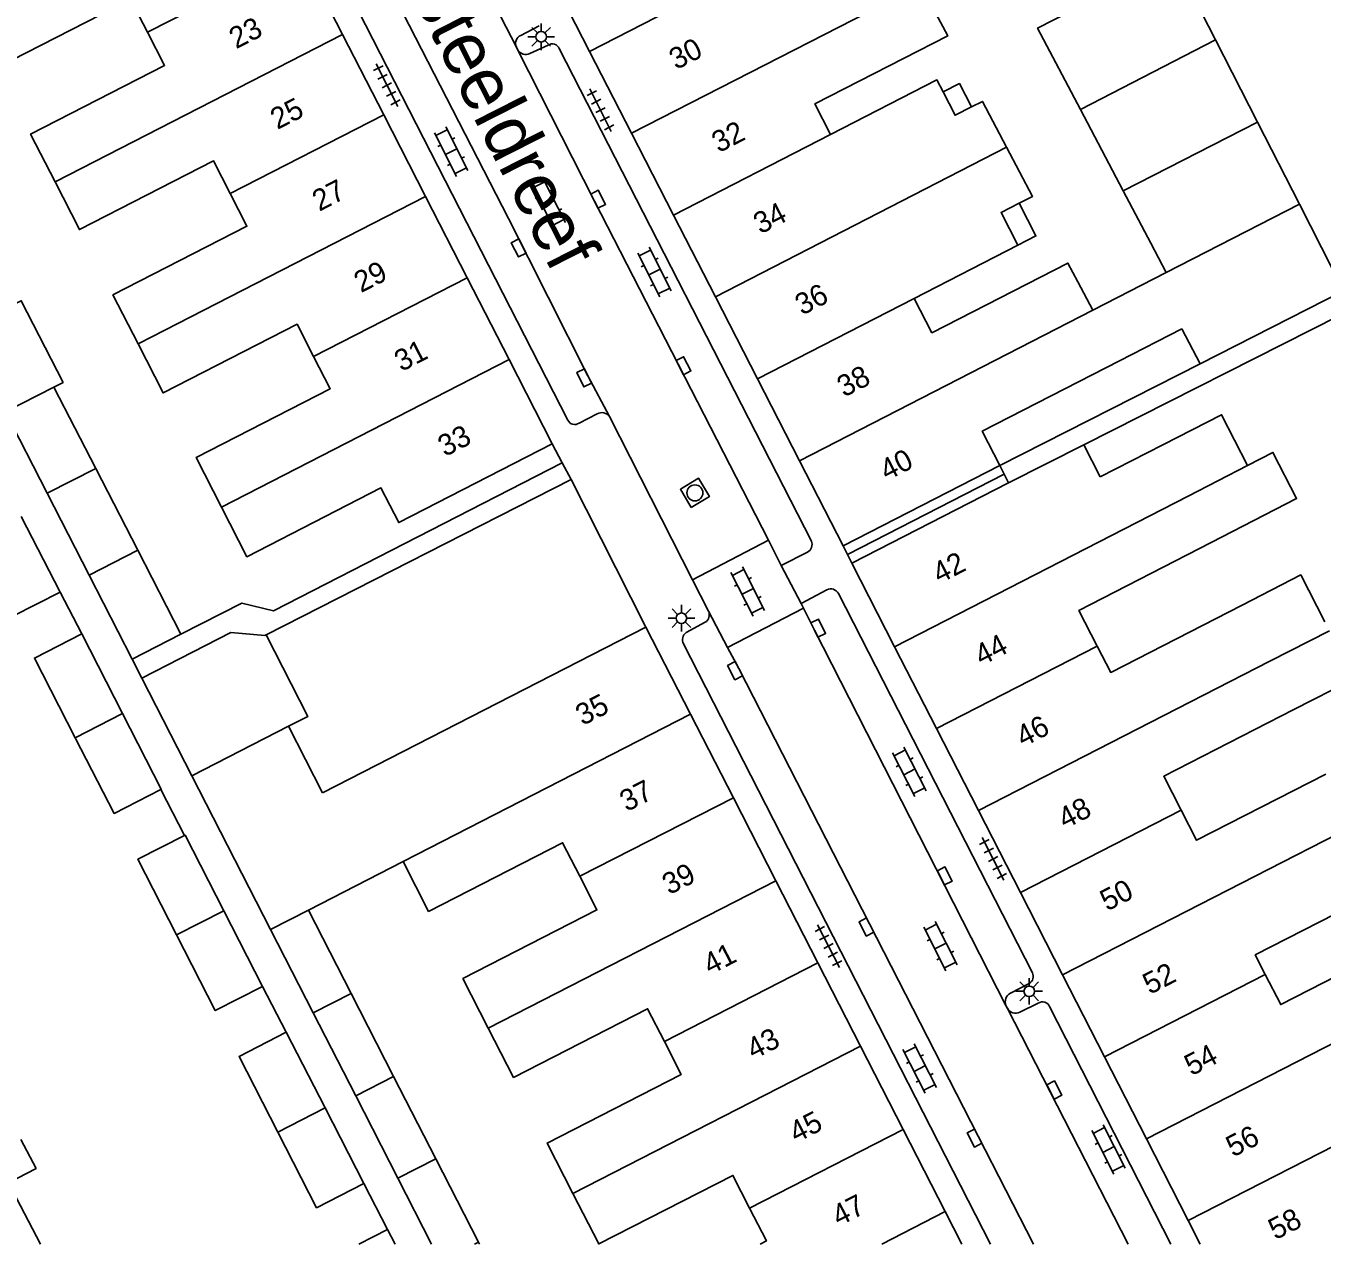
# Model space of a CAD drawing. Extents: x 132999 to 136000, y 398499 to 400501.
# Drawn here: x 133446.8 to 133507.8, y 398500 to 398557.3 of the extents above; entities that cross this region are included whole.
import ezdxf

# ---------------------------------------------------------------- set-up
doc = ezdxf.new("R2010")
doc.units = 0
for name, color, linetype in [('gg-afsc-erfafscheiding', 7, 'Continuous'), ('gg-anno-huisnummerreeks BGT', 7, 'Continuous'), ('gg-anno-openbare ruimte label', 7, 'Continuous'), ('gg-bbg-bijgebouw', 7, 'Continuous'), ('gg-bbg-gedigitaliseerde bebouwing', 7, 'Continuous'), ('gg-bbg-gedigitaliseerde bebouwing onder overbouw', 7, 'Continuous'), ('gg-bbg-gedigitaliseerde bijgebouw', 7, 'Continuous'), ('gg-bbg-gedigitaliseerde overbouw', 7, 'Continuous'), ('gg-bbg-hoofdgebouw', 7, 'Continuous'), ('gg-bbg-luifel en loopbrug', 7, 'Continuous'), ('gg-bbg-pand overbouw', 7, 'Continuous'), ('gg-bbg-tussenscheiding', 7, 'Continuous'), ('gg-bbg-tussenscheiding niveau 01', 7, 'Continuous'), ('gg-knt-verharding', 7, 'Continuous'), ('gt-grn-weggrens', 7, 'Continuous'), ('gt-symb-klinker verharding', 7, 'Continuous'), ('gt-symb-kolk', 7, 'Continuous'), ('gt-symb-lichtmast', 7, 'Continuous'), ('gt-symb-rioolschacht', 7, 'Continuous'), ('gt-symb-tegel verharding', 7, 'Continuous')]:
    doc.layers.add(name, color=color, linetype=linetype)

# ---------------------------------------------------------------- blocks, each defined once
blk = doc.blocks.new('gt0-KOLK')
at = {"layer": 'gt-symb-kolk'}
blk.add_lwpolyline([(0, 0), (0.375, 0), (0.375, 0.4), (-0.375, 0.4), (-0.375, 0), (0, 0)], dxfattribs=at)
blk = doc.blocks.new('gt0-TEG1')
at = {"layer": 'gt-symb-tegel verharding'}
for p, q in [((-1.125, 0), (1.125, 0)), ((-0.9, -0.25), (-0.9, 0.25)), ((-0.45, -0.25), (-0.45, 0.25)), ((0, -0.25), (0, 0.25)), ((0.45, -0.25), (0.45, 0.25)), ((0.9, -0.25), (0.9, 0.25))]:
    blk.add_line(p, q, dxfattribs=at)
blk = doc.blocks.new('gt0-KL1')
at = {"layer": 'gt-symb-klinker verharding'}
for p, q in [((-1.15, 0.3), (1.15, 0.3)), ((-1, -0.3), (-1, 0.3)), ((-0.5, 0.3), (-0.5, 0.45)), ((0, -0.3), (0, 0.3)), ((0.5, 0.3), (0.5, 0.45)), ((1, -0.3), (1, 0.3)), ((-1.15, -0.3), (1.15, -0.3)), ((-0.5, -0.45), (-0.5, -0.3)), ((0.5, -0.45), (0.5, -0.3))]:
    blk.add_line(p, q, dxfattribs=at)
blk = doc.blocks.new('gt0-LMAST')
at = {"layer": 'gt-symb-lichtmast'}
for p, q in [((-0.005, 0.246), (-0.005, 0.621)), ((-0.182, 0.173), (-0.447, 0.438)), ((0.172, 0.173), (0.437, 0.438)), ((-0.255, -0.004), (-0.63, -0.004)), ((-0.182, -0.181), (-0.447, -0.446)), ((-0.005, -0.254), (-0.005, -0.629)), ((0.437, -0.446), (0.172, -0.181)), ((0.245, -0.004), (0.62, -0.004))]:
    blk.add_line(p, q, dxfattribs=at)
blk.add_circle((-0.005, -0.004), 0.25, dxfattribs=at)
blk = doc.blocks.new('gt0-RS')
at = {"layer": 'gt-symb-rioolschacht'}
blk.add_lwpolyline([(-0.5, -0.5), (0.5, -0.5), (0.5, 0.5), (-0.5, 0.5)], close=True, dxfattribs=at)
blk.add_circle((0, 0), 0.375, dxfattribs=at)

msp = doc.modelspace()

# ---------------------------------------------------------------- linework, layer by layer
at = {"layer": 'gg-afsc-erfafscheiding'}
for p, q in [((133508.606, 398543.678), (133496.575, 398537.6)), ((133502.054, 398541.403), (133492.623, 398536.616)), ((133472.037, 398536.741), (133471.566, 398537.639)), ((133472.458, 398535.969), (133458.114, 398528.653)), ((133475.979, 398529.023), (133472.458, 398535.969)), ((133448.409, 398530.669), (133449.432, 398528.7)), ((133453.152, 398521.383), (133454.258, 398519.224)), ((133457.939, 398512.121), (133459.056, 398509.967)), ((133462.703, 398502.846), (133463.821, 398500.692))]:
    msp.add_line(p, q, dxfattribs=at)
msp.add_lwpolyline([(133454.099, 398528.68), (133456.969, 398530.152), (133458.453, 398529.787), (133472.037, 398536.741)], dxfattribs=at)
at = {"layer": 'gg-bbg-bijgebouw'}
for p, q in [((133502.781, 398556.636), (133504.751, 398552.774)), ((133504.751, 398552.774), (133506.722, 398548.91))]:
    msp.add_line(p, q, dxfattribs=at)
msp.add_lwpolyline([(133500.043, 398560.076), (133500.831, 398560.459), (133502.781, 398556.636)], dxfattribs=at)
at = {"layer": 'gg-bbg-gedigitaliseerde bebouwing'}
for p, q in [((133488.6, 398544.484), (133493.475, 398546.985)), ((133500.457, 398545.694), (133497.003, 398543.921)), ((133497.003, 398543.921), (133496.294, 398545.263)), ((133498.262, 398541.541), (133501.191, 398543.042)), ((133501.191, 398543.042), (133502.054, 398541.403)), ((133496.575, 398537.6), (133493.036, 398535.81)), ((133496.575, 398537.6), (133497.352, 398536.082)), ((133497.352, 398536.082), (133500.294, 398537.589)), ((133460.759, 398521.23), (133475.979, 398529.023)), ((133506.464, 398525.14), (133509.283, 398526.591)), ((133459.159, 398524.354), (133460.759, 398521.23)), ((133454.612, 398522.026), (133458.316, 398514.795)), ((133464.548, 398517.987), (133460.096, 398515.707))]:
    msp.add_line(p, q, dxfattribs=at)
for points in [[(133488.912, 398559.222), (133490.176, 398556.831), (133483.922, 398553.626), (133484.657, 398552.192)], [(133444.364, 398557.399), (133445.426, 398555.328), (133451.732, 398558.56), (133452.532, 398557)], [(133452.532, 398557), (133453.331, 398555.441), (133447.023, 398552.207), (133448.173, 398549.964)], [(133484.657, 398552.192), (133489.664, 398554.761), (133489.954, 398554.195)], [(133489.954, 398554.195), (133490.52, 398553.092), (133491.29, 398553.486)], [(133491.29, 398553.486), (133491.805, 398553.75), (133492.949, 398551.587)], [(133492.949, 398551.587), (133494.168, 398549.281), (133493.541, 398548.96)], [(133448.173, 398549.964), (133449.323, 398547.72), (133455.628, 398550.952), (133456.416, 398549.415)], [(133456.416, 398549.415), (133457.204, 398547.878), (133450.896, 398544.644), (133452.078, 398542.338)], [(133493.475, 398546.985), (133492.687, 398548.522), (133493.541, 398548.96)], [(133488.6, 398544.484), (133489.429, 398542.865), (133495.828, 398546.143), (133496.294, 398545.263)], [(133452.078, 398542.338), (133453.26, 398540.033), (133459.564, 398543.265), (133460.342, 398541.748)], [(133460.342, 398541.748), (133461.12, 398540.231), (133454.812, 398536.996), (133456.008, 398534.664)], [(133498.262, 398541.541), (133491.797, 398538.229), (133492.623, 398536.616)], [(133500.294, 398537.589), (133503.059, 398539.012), (133504.288, 398536.624)], [(133456.008, 398534.664), (133457.204, 398532.332), (133463.508, 398535.565), (133464.344, 398533.935), (133471.566, 398537.639)], [(133502.571, 398532.996), (133506.592, 398535.065), (133505.476, 398537.234), (133504.288, 398536.624)], [(133502.571, 398532.996), (133496.349, 398529.808), (133497.214, 398528.12)], [(133504.029, 398530.055), (133506.79, 398531.476), (133507.917, 398529.268)], [(133497.214, 398528.12), (133497.845, 398526.887), (133504.029, 398530.055)], [(133506.464, 398525.14), (133500.344, 398522.006), (133501.161, 398520.411)], [(133501.161, 398520.411), (133501.887, 398518.994), (133507.967, 398522.109)], [(133472.864, 398517.298), (133472.055, 398518.877), (133465.746, 398515.647), (133464.548, 398517.987)], [(133513.159, 398518.95), (133510.26, 398517.501), (133510.668, 398516.684), (133504.649, 398513.601), (133505.118, 398512.685)], [(133468.555, 398510.162), (133467.364, 398512.489), (133473.672, 398515.719), (133472.864, 398517.298)], [(133505.118, 398512.685), (133505.845, 398511.266), (133511.824, 398514.327)], [(133476.845, 398509.522), (133476.055, 398511.066), (133469.746, 398507.836), (133468.555, 398510.162)], [(133472.544, 398502.376), (133471.328, 398504.751), (133477.635, 398507.979), (133476.845, 398509.522)], [(133446.568, 398504.916), (133447.28, 398503.555), (133445.991, 398502.881), (133447.497, 398500)], [(133480.856, 398501.689), (133480.066, 398503.233), (133473.758, 398500.004), (133472.544, 398502.376)], [(133481.354, 398500), (133481.645, 398500.149), (133480.856, 398501.689)]]:
    msp.add_lwpolyline(points, dxfattribs=at)
at = {"layer": 'gg-bbg-gedigitaliseerde bebouwing onder overbouw'}
for p, q in [((133492.623, 398536.616), (133485.25, 398532.841)), ((133485.66, 398532.031), (133493.036, 398535.81))]:
    msp.add_line(p, q, dxfattribs=at)
at = {"layer": 'gg-bbg-gedigitaliseerde bijgebouw'}
for p, q in [((133496.418, 398553.369), (133498.437, 398549.533)), ((133498.437, 398549.533), (133499.732, 398547.072)), ((133499.732, 398547.072), (133500.457, 398545.694)), ((133448.123, 398540.31), (133450.088, 398536.486)), ((133445.845, 398539.14), (133447.805, 398535.313)), ((133450.088, 398536.486), (133447.805, 398535.313)), ((133446.585, 398534.23), (133448.409, 398530.669)), ((133452.065, 398532.639), (133449.777, 398531.464)), ((133452.065, 398532.639), (133454.099, 398528.68)), ((133449.777, 398531.464), (133451.806, 398527.504)), ((133449.432, 398528.7), (133451.35, 398524.955)), ((133454.099, 398528.68), (133451.806, 398527.504)), ((133452.262, 398526.613), (133454.612, 398522.026)), ((133456.115, 398515.681), (133457.939, 398512.121)), ((133460.096, 398515.707), (133462.103, 398511.788)), ((133458.316, 398514.795), (133460.323, 398510.876)), ((133464.103, 398507.883), (133462.103, 398511.788)), ((133460.323, 398510.876), (133462.323, 398506.972)), ((133459.056, 398509.967), (133460.88, 398506.406)), ((133464.103, 398507.883), (133466.085, 398504.014)), ((133462.323, 398506.972), (133464.305, 398503.102)), ((133460.88, 398506.406), (133462.703, 398502.846)), ((133466.085, 398504.014), (133468.091, 398500.096)), ((133464.305, 398503.102), (133465.894, 398500)), ((133462.47, 398500), (133463.821, 398500.692)), ((133463.821, 398500.692), (133464.175, 398500)), ((133468.091, 398500.096), (133468.14, 398500))]:
    msp.add_line(p, q, dxfattribs=at)
for points in [[(133495.939, 398557.976), (133494.405, 398557.192), (133496.418, 398553.369)], [(133448.123, 398540.31), (133448.555, 398540.532), (133446.582, 398544.373), (133446.281, 398544.219)], [(133444.361, 398533.09), (133446.184, 398529.53), (133448.409, 398530.669)], [(133449.125, 398523.815), (133447.207, 398527.56), (133449.432, 398528.7)], [(133452.262, 398526.613), (133456.446, 398528.759), (133458.05, 398528.62), (133458.114, 398528.653)], [(133458.114, 398528.653), (133460.069, 398524.82), (133459.159, 398524.354)], [(133451.35, 398524.955), (133453.174, 398521.395), (133453.152, 398521.383)], [(133449.125, 398523.815), (133450.949, 398520.255), (133453.152, 398521.383)], [(133453.89, 398514.541), (133452.066, 398518.101), (133454.258, 398519.224)], [(133456.115, 398515.681), (133454.291, 398519.241), (133454.258, 398519.224)], [(133453.89, 398514.541), (133455.714, 398510.981), (133457.939, 398512.121)], [(133458.655, 398505.267), (133456.831, 398508.827), (133459.056, 398509.967)], [(133458.655, 398505.267), (133460.478, 398501.707), (133462.703, 398502.846)]]:
    msp.add_lwpolyline(points, dxfattribs=at)
at = {"layer": 'gg-bbg-gedigitaliseerde overbouw'}
for p, q in [((133492.83, 398536.213), (133492.623, 398536.616)), ((133493.036, 398535.81), (133492.83, 398536.213))]:
    msp.add_line(p, q, dxfattribs=at)
at = {"layer": 'gg-bbg-hoofdgebouw'}
for p, q in [((133461.702, 398556.899), (133459.754, 398560.703)), ((133473.324, 398556.101), (133471.348, 398559.955)), ((133463.639, 398553.118), (133461.702, 398556.899)), ((133475.299, 398552.248), (133473.324, 398556.101)), ((133465.607, 398549.275), (133463.639, 398553.118)), ((133477.271, 398548.403), (133475.299, 398552.248)), ((133467.565, 398545.452), (133465.607, 398549.275)), ((133479.247, 398544.55), (133477.271, 398548.403)), ((133506.722, 398548.91), (133508.797, 398544.843)), ((133469.537, 398541.602), (133467.565, 398545.452)), ((133508.797, 398544.843), (133502.054, 398541.403)), ((133481.222, 398540.697), (133479.247, 398544.55)), ((133471.566, 398537.639), (133469.537, 398541.602)), ((133483.198, 398536.844), (133481.222, 398540.697)), ((133485.25, 398532.841), (133483.198, 398536.844)), ((133485.66, 398532.031), (133487.674, 398528.098)), ((133475.979, 398529.023), (133478.081, 398524.918)), ((133487.674, 398528.098), (133489.647, 398524.244)), ((133478.081, 398524.918), (133480.089, 398520.997)), ((133489.647, 398524.244), (133491.621, 398520.39)), ((133480.089, 398520.997), (133482.089, 398517.091)), ((133491.621, 398520.39), (133493.594, 398516.536)), ((133482.089, 398517.091), (133484.071, 398513.221)), ((133493.594, 398516.536), (133495.576, 398512.664)), ((133484.071, 398513.221), (133486.077, 398509.304)), ((133495.576, 398512.664), (133497.55, 398508.81)), ((133486.077, 398509.304), (133488.082, 398505.389)), ((133497.55, 398508.81), (133499.524, 398504.955)), ((133488.082, 398505.389), (133490.059, 398501.529)), ((133499.524, 398504.955), (133501.497, 398501.102)), ((133490.059, 398501.529), (133490.842, 398500)), ((133501.497, 398501.102), (133502.061, 398500))]:
    msp.add_line(p, q, dxfattribs=at)
at = {"layer": 'gg-bbg-luifel en loopbrug'}
for p, q in [((133450.088, 398536.486), (133452.065, 398532.639)), ((133447.805, 398535.313), (133449.777, 398531.464))]:
    msp.add_line(p, q, dxfattribs=at)
for points in [[(133489.954, 398554.195), (133490.725, 398554.589), (133491.29, 398553.486)], [(133493.541, 398548.96), (133494.329, 398547.423), (133493.475, 398546.985)]]:
    msp.add_lwpolyline(points, dxfattribs=at)
at = {"layer": 'gg-bbg-pand overbouw'}
for p, q in [((133485.25, 398532.841), (133485.455, 398532.436)), ((133485.455, 398532.436), (133485.66, 398532.031))]:
    msp.add_line(p, q, dxfattribs=at)
at = {"layer": 'gg-bbg-tussenscheiding'}
for p, q in [((133452.532, 398557), (133459.754, 398560.703)), ((133480.712, 398559.888), (133473.324, 398556.101)), ((133488.912, 398559.222), (133475.299, 398552.248)), ((133461.702, 398556.899), (133448.173, 398549.964)), ((133502.781, 398556.636), (133496.418, 398553.369)), ((133456.416, 398549.415), (133463.639, 398553.118)), ((133498.437, 398549.533), (133504.751, 398552.774)), ((133484.657, 398552.192), (133477.271, 398548.403)), ((133492.949, 398551.587), (133479.247, 398544.55)), ((133465.607, 398549.275), (133452.078, 398542.338)), ((133500.457, 398545.694), (133506.722, 398548.91)), ((133460.342, 398541.748), (133467.565, 398545.452)), ((133488.6, 398544.484), (133481.222, 398540.697)), ((133497.003, 398543.921), (133483.198, 398536.844)), ((133469.537, 398541.602), (133456.008, 398534.664)), ((133448.123, 398540.31), (133445.845, 398539.14)), ((133501.485, 398535.186), (133504.288, 398536.624)), ((133487.674, 398528.098), (133501.485, 398535.186)), ((133505.337, 398527.414), (133508.132, 398528.846)), ((133489.647, 398524.244), (133497.214, 398528.12)), ((133491.621, 398520.39), (133505.337, 398527.414)), ((133449.125, 398523.815), (133451.35, 398524.955)), ((133478.081, 398524.918), (133464.548, 398517.987)), ((133454.612, 398522.026), (133459.159, 398524.354)), ((133472.864, 398517.298), (133480.089, 398520.997)), ((133495.576, 398512.664), (133512.07, 398521.118)), ((133493.594, 398516.536), (133501.161, 398520.411)), ((133482.089, 398517.091), (133468.555, 398510.162)), ((133453.89, 398514.541), (133456.115, 398515.681)), ((133460.096, 398515.707), (133458.316, 398514.795)), ((133476.845, 398509.522), (133484.071, 398513.221)), ((133497.55, 398508.81), (133505.118, 398512.685)), ((133499.524, 398504.955), (133513.038, 398511.876)), ((133462.103, 398511.788), (133460.323, 398510.876)), ((133486.077, 398509.304), (133472.544, 398502.376)), ((133462.323, 398506.972), (133464.103, 398507.883)), ((133458.655, 398505.267), (133460.88, 398506.406)), ((133480.856, 398501.689), (133488.082, 398505.389)), ((133501.497, 398501.102), (133509.065, 398504.977)), ((133464.305, 398503.102), (133466.085, 398504.014)), ((133487.073, 398500), (133490.059, 398501.529)), ((133467.903, 398500), (133468.091, 398500.096))]:
    msp.add_line(p, q, dxfattribs=at)
at = {"layer": 'gg-bbg-tussenscheiding niveau 01'}
msp.add_line((133485.455, 398532.436), (133492.83, 398536.213), dxfattribs=at)
at = {"layer": 'gg-knt-verharding'}
for p, q in [((133469.887, 398556.296), (133465.374, 398565.07)), ((133472.307, 398538.755), (133459.754, 398563.28)), ((133470.956, 398557.297), (133470.086, 398556.851)), ((133470.515, 398555.993), (133471.384, 398556.392)), ((133469.887, 398556.296), (133469.955, 398556.155)), ((133471.89, 398556.235), (133483.764, 398533.063)), ((133472.832, 398538.611), (133473.689, 398539.049)), ((133474.265, 398538.92), (133478.172, 398531.246)), ((133478.172, 398531.246), (133481.739, 398533.102)), ((133482.346, 398531.922), (133481.739, 398533.102)), ((133483.585, 398532.542), (133482.346, 398531.922)), ((133482.346, 398531.922), (133483.276, 398530.137)), ((133478.172, 398531.246), (133478.92, 398529.777)), ((133483.276, 398530.137), (133484.489, 398530.773)), ((133483.391, 398529.906), (133483.276, 398530.137)), ((133485.03, 398530.594), (133494.16, 398512.763)), ((133479.819, 398528.064), (133478.92, 398529.777)), ((133483.391, 398529.906), (133479.819, 398528.064)), ((133478.756, 398529.246), (133477.865, 398528.76)), ((133477.748, 398528.236), (133492.186, 398500)), ((133451.806, 398527.504), (133452.262, 398526.613)), ((133493.125, 398511.802), (133494.003, 398512.263)), ((133492.918, 398511.225), (133492.988, 398511.088)), ((133493.571, 398510.912), (133494.435, 398511.333)), ((133492.988, 398511.088), (133498.666, 398500)), ((133494.971, 398511.169), (133500.677, 398500))]:
    msp.add_line(p, q, dxfattribs=at)
for points in [[(133461.834, 398563.255), (133463.377, 398560.179), (133469.504, 398548.244)], [(133469.955, 398556.155), (133473.549, 398549.053), (133481.739, 398533.102)], [(133469.504, 398548.244), (133473.248, 398540.835), (133474.265, 398538.92)], [(133483.391, 398529.906), (133483.901, 398528.881), (133492.918, 398511.225)], [(133479.819, 398528.064), (133480.343, 398527.065), (133491.614, 398505.076), (133494.207, 398500)]]:
    msp.add_lwpolyline(points, dxfattribs=at)
for centre, radius, start, end in [((133470.25, 398556.479), 0.407, 113.8023, 206.74624), ((133471.576, 398556.116), 0.336, 20.75718, 124.76702), ((133470.332, 398556.411), 0.456, 214.11959, 293.6116), ((133472.629, 398538.899), 0.352, 204.04691, 305.2767), ((133473.908, 398538.676), 0.433, 34.38864, 120.36423), ((133483.364, 398532.909), 0.429, 301.03721, 21.04042), ((133484.672, 398530.418), 0.399, 26.1728, 117.21167), ((133478.55, 398529.6), 0.41, 300.12004, 25.55323), ((133478.098, 398528.433), 0.402, 125.4765, 209.35014), ((133493.835, 398512.59), 0.368, 297.17699, 27.95844), ((133493.348, 398511.396), 0.463, 118.78226, 201.74662), ((133494.635, 398511.029), 0.364, 22.68038, 123.29452), ((133493.368, 398511.293), 0.431, 208.30241, 298.10085)]:
    msp.add_arc(centre, radius, start, end, dxfattribs=at)
at = {"layer": 'gt-grn-weggrens'}
msp.add_line((133472.458, 398535.969), (133472.037, 398536.741), dxfattribs=at)

# ---------------------------------------------------------------- block references
at = {"layer": 'gt-symb-klinker verharding'}
for p, rotation in [((133466.813, 398551.382), -63.20443508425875), ((133471.399, 398548.943), -63.20443508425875), ((133476.375, 398545.723), -63.20443508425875), ((133480.765, 398530.697), -63.20443508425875), ((133488.372, 398522.213), -62.87123393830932), ((133489.836, 398514.016), -62.87123394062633), ((133488.86, 398508.258), -62.87123394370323), ((133497.741, 398504.451), -62.87123394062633)]:
    msp.add_blockref('gt0-KL1', p, dxfattribs=dict(at, rotation=rotation))
at = {"layer": 'gt-symb-kolk'}
for p, rotation in [((133473.549, 398549.053), -63.15706141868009), ((133470.168, 398546.95), 117.17858882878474), ((133477.566, 398541.22), -62.85031830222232), ((133473.248, 398540.835), 116.73467159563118), ((133483.901, 398528.881), -63.554044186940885), ((133480.343, 398527.065), 117.68750489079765), ((133489.859, 398517.224), -62.92967630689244), ((133486.53, 398515.005), 117.16054492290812), ((133495.012, 398507.154), -62.78532372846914), ((133491.614, 398505.076), 117.08836815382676)]:
    msp.add_blockref('gt0-KOLK', p, dxfattribs=dict(at, rotation=rotation))
at = {"layer": 'gt-symb-lichtmast'}
for p in [(133471.05, 398556.792), (133477.651, 398529.441), (133494.017, 398511.892)]:
    msp.add_blockref('gt0-LMAST', p, dxfattribs=at)
at = {"layer": 'gt-symb-rioolschacht', "rotation": 30.907015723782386}
msp.add_blockref('gt0-RS', (133478.281, 398535.334), dxfattribs=at)
at = {"layer": 'gt-symb-tegel verharding'}
for p, rotation in [((133463.788, 398554.504), -63.20443508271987), ((133473.838, 398553.333), -63.20443508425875), ((133492.311, 398518.115), 117.12876605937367), ((133484.566, 398514.016), -62.871233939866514)]:
    msp.add_blockref('gt0-TEG1', p, dxfattribs=dict(at, rotation=rotation))

# ---------------------------------------------------------------- texts
at = {"layer": 'gg-anno-huisnummerreeks BGT'}
for s, p in [('23', (133456.695, 398556.196)), ('30', (133477.399, 398555.215)), ('25', (133458.638, 398552.403)), ('32', (133479.403, 398551.307)), ('27', (133460.609, 398548.554)), ('34', (133481.363, 398547.486)), ('29', (133462.57, 398544.725)), ('36', (133483.322, 398543.664)), ('31', (133464.47, 398541.016)), ('38', (133485.298, 398539.812)), ('33', (133466.518, 398537.015)), ('40', (133487.312, 398535.884)), ('42', (133489.787, 398531.043)), ('44', (133491.766, 398527.178)), ('35', (133472.997, 398524.365)), ('46', (133493.722, 398523.357)), ('37', (133475.071, 398520.315)), ('48', (133495.696, 398519.502)), ('39', (133477.073, 398516.406)), ('50', (133497.673, 398515.64)), ('41', (133478.999, 398512.645)), ('52', (133499.682, 398511.717)), ('43', (133481.041, 398508.657)), ('54', (133501.642, 398507.89)), ('45', (133483.047, 398504.741)), ('56', (133503.599, 398504.068)), ('47', (133485.056, 398500.817)), ('58', (133505.592, 398500.175))]:
    msp.add_text(s, height=1, rotation=27.1, dxfattribs=at).set_placement(p)
at = {"layer": 'gg-anno-openbare ruimte label'}
msp.add_text('Kasteeldreef', height=2.5, rotation=296.9, dxfattribs=at).set_placement((133463.112, 398562.334))

doc.saveas('drawing.dxf')
